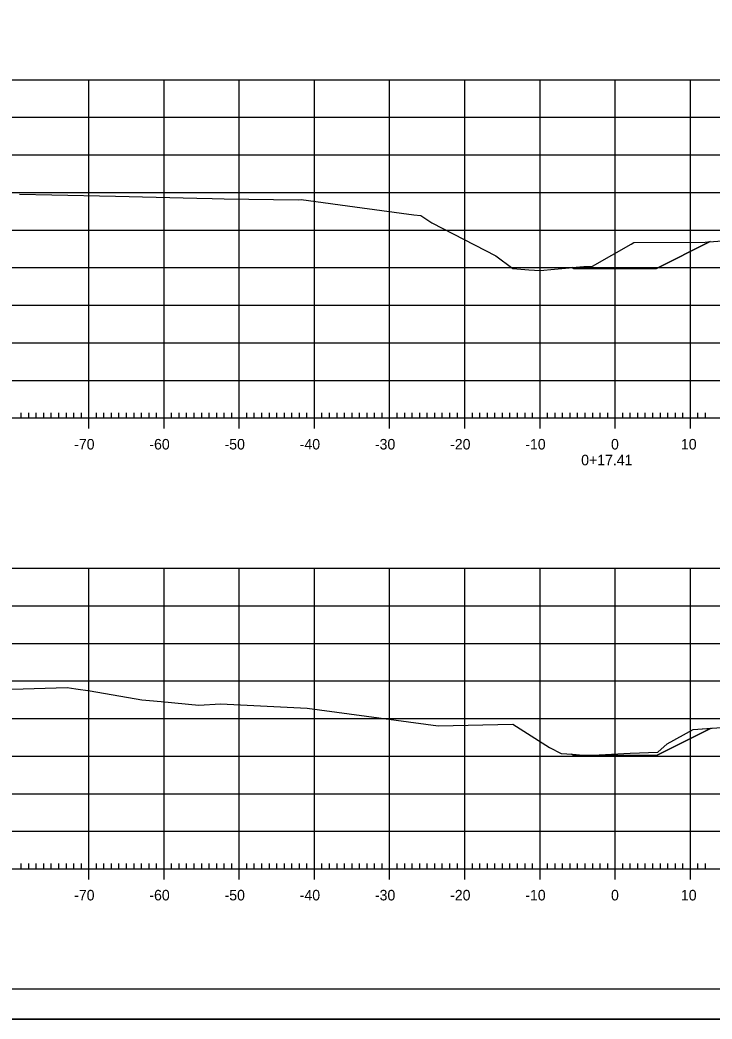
# Model space of a CAD drawing. Extents: x 1360146 to 1361431, y 631444 to 632352.
# Drawn here: x 1361162.4 to 1361254.5, y 631924.1 to 632057 of the extents above; entities that cross this region are included whole.
import ezdxf

# ---------------------------------------------------------------- set-up
doc = ezdxf.new("R2010")
doc.units = 0
for name, color, linetype in [('R_Axis', 7, 'Continuous'), ('R_Axis Annot', 7, 'Continuous'), ('R_Border', 7, 'Continuous'), ('R_Exist Surface', 7, 'Continuous'), ('R_Fin Surface', 7, 'Continuous'), ('R_Grid', 7, 'Continuous'), ('R_No Plot', 7, 'Continuous')]:
    doc.layers.add(name, color=color, linetype=linetype)

msp = doc.modelspace()

# ---------------------------------------------------------------- linework, layer by layer
at = {"layer": 'R_Axis'}
for p, q in [((1361101.6, 632004.09), (1361381.6, 632004.09)), ((1361162.6, 632004.09), (1361162.6, 632004.79)), ((1361163.6, 632004.09), (1361163.6, 632004.79)), ((1361164.6, 632004.09), (1361164.6, 632004.79)), ((1361165.6, 632004.09), (1361165.6, 632004.79)), ((1361166.6, 632004.09), (1361166.6, 632004.79)), ((1361167.6, 632004.09), (1361167.6, 632004.79)), ((1361168.6, 632004.09), (1361168.6, 632004.79)), ((1361169.6, 632004.09), (1361169.6, 632004.79)), ((1361170.6, 632004.09), (1361170.6, 632004.79)), ((1361171.6, 632002.69), (1361171.6, 632004.09)), ((1361172.6, 632004.09), (1361172.6, 632004.79)), ((1361173.6, 632004.09), (1361173.6, 632004.79)), ((1361174.6, 632004.09), (1361174.6, 632004.79)), ((1361175.6, 632004.09), (1361175.6, 632004.79)), ((1361176.6, 632004.09), (1361176.6, 632004.79)), ((1361177.6, 632004.09), (1361177.6, 632004.79)), ((1361178.6, 632004.09), (1361178.6, 632004.79)), ((1361179.6, 632004.09), (1361179.6, 632004.79)), ((1361180.6, 632004.09), (1361180.6, 632004.79)), ((1361181.6, 632002.69), (1361181.6, 632004.09)), ((1361182.6, 632004.09), (1361182.6, 632004.79)), ((1361183.6, 632004.09), (1361183.6, 632004.79)), ((1361184.6, 632004.09), (1361184.6, 632004.79)), ((1361185.6, 632004.09), (1361185.6, 632004.79)), ((1361186.6, 632004.09), (1361186.6, 632004.79)), ((1361187.6, 632004.09), (1361187.6, 632004.79)), ((1361188.6, 632004.09), (1361188.6, 632004.79)), ((1361189.6, 632004.09), (1361189.6, 632004.79)), ((1361190.6, 632004.09), (1361190.6, 632004.79)), ((1361191.6, 632002.69), (1361191.6, 632004.09)), ((1361192.6, 632004.09), (1361192.6, 632004.79)), ((1361193.6, 632004.09), (1361193.6, 632004.79)), ((1361194.6, 632004.09), (1361194.6, 632004.79)), ((1361195.6, 632004.09), (1361195.6, 632004.79)), ((1361196.6, 632004.09), (1361196.6, 632004.79)), ((1361197.6, 632004.09), (1361197.6, 632004.79)), ((1361198.6, 632004.09), (1361198.6, 632004.79)), ((1361199.6, 632004.09), (1361199.6, 632004.79)), ((1361200.6, 632004.09), (1361200.6, 632004.79)), ((1361201.6, 632002.69), (1361201.6, 632004.09)), ((1361202.6, 632004.09), (1361202.6, 632004.79)), ((1361203.6, 632004.09), (1361203.6, 632004.79)), ((1361204.6, 632004.09), (1361204.6, 632004.79)), ((1361205.6, 632004.09), (1361205.6, 632004.79)), ((1361206.6, 632004.09), (1361206.6, 632004.79)), ((1361207.6, 632004.09), (1361207.6, 632004.79)), ((1361208.6, 632004.09), (1361208.6, 632004.79)), ((1361209.6, 632004.09), (1361209.6, 632004.79)), ((1361210.6, 632004.09), (1361210.6, 632004.79)), ((1361211.6, 632002.69), (1361211.6, 632004.09)), ((1361212.6, 632004.09), (1361212.6, 632004.79)), ((1361213.6, 632004.09), (1361213.6, 632004.79)), ((1361214.6, 632004.09), (1361214.6, 632004.79)), ((1361215.6, 632004.09), (1361215.6, 632004.79)), ((1361216.6, 632004.09), (1361216.6, 632004.79)), ((1361217.6, 632004.09), (1361217.6, 632004.79)), ((1361218.6, 632004.09), (1361218.6, 632004.79)), ((1361219.6, 632004.09), (1361219.6, 632004.79)), ((1361220.6, 632004.09), (1361220.6, 632004.79)), ((1361221.6, 632002.69), (1361221.6, 632004.09)), ((1361222.6, 632004.09), (1361222.6, 632004.79)), ((1361223.6, 632004.09), (1361223.6, 632004.79)), ((1361224.6, 632004.09), (1361224.6, 632004.79)), ((1361225.6, 632004.09), (1361225.6, 632004.79)), ((1361226.6, 632004.09), (1361226.6, 632004.79)), ((1361227.6, 632004.09), (1361227.6, 632004.79)), ((1361228.6, 632004.09), (1361228.6, 632004.79)), ((1361229.6, 632004.09), (1361229.6, 632004.79)), ((1361230.6, 632004.09), (1361230.6, 632004.79)), ((1361231.6, 632002.69), (1361231.6, 632004.09)), ((1361232.6, 632004.09), (1361232.6, 632004.79)), ((1361233.6, 632004.09), (1361233.6, 632004.79)), ((1361234.6, 632004.09), (1361234.6, 632004.79)), ((1361235.6, 632004.09), (1361235.6, 632004.79)), ((1361236.6, 632004.09), (1361236.6, 632004.79)), ((1361237.6, 632004.09), (1361237.6, 632004.79)), ((1361238.6, 632004.09), (1361238.6, 632004.79)), ((1361239.6, 632004.09), (1361239.6, 632004.79)), ((1361240.6, 632004.09), (1361240.6, 632004.79)), ((1361241.6, 632002.69), (1361241.6, 632004.09)), ((1361242.6, 632004.09), (1361242.6, 632004.79)), ((1361243.6, 632004.09), (1361243.6, 632004.79)), ((1361244.6, 632004.09), (1361244.6, 632004.79)), ((1361245.6, 632004.09), (1361245.6, 632004.79)), ((1361246.6, 632004.09), (1361246.6, 632004.79)), ((1361247.6, 632004.09), (1361247.6, 632004.79)), ((1361248.6, 632004.09), (1361248.6, 632004.79)), ((1361249.6, 632004.09), (1361249.6, 632004.79)), ((1361250.6, 632004.09), (1361250.6, 632004.79)), ((1361251.6, 632002.69), (1361251.6, 632004.09)), ((1361252.6, 632004.09), (1361252.6, 632004.79)), ((1361253.6, 632004.09), (1361253.6, 632004.79)), ((1361162.6, 631944.09), (1361162.6, 631944.79)), ((1361163.6, 631944.09), (1361163.6, 631944.79)), ((1361164.6, 631944.09), (1361164.6, 631944.79)), ((1361165.6, 631944.09), (1361165.6, 631944.79)), ((1361166.6, 631944.09), (1361166.6, 631944.79)), ((1361167.6, 631944.09), (1361167.6, 631944.79)), ((1361168.6, 631944.09), (1361168.6, 631944.79)), ((1361169.6, 631944.09), (1361169.6, 631944.79)), ((1361170.6, 631944.09), (1361170.6, 631944.79)), ((1361172.6, 631944.09), (1361172.6, 631944.79)), ((1361173.6, 631944.09), (1361173.6, 631944.79)), ((1361174.6, 631944.09), (1361174.6, 631944.79)), ((1361175.6, 631944.09), (1361175.6, 631944.79)), ((1361176.6, 631944.09), (1361176.6, 631944.79)), ((1361177.6, 631944.09), (1361177.6, 631944.79)), ((1361178.6, 631944.09), (1361178.6, 631944.79)), ((1361179.6, 631944.09), (1361179.6, 631944.79)), ((1361180.6, 631944.09), (1361180.6, 631944.79)), ((1361182.6, 631944.09), (1361182.6, 631944.79)), ((1361183.6, 631944.09), (1361183.6, 631944.79)), ((1361184.6, 631944.09), (1361184.6, 631944.79)), ((1361185.6, 631944.09), (1361185.6, 631944.79)), ((1361186.6, 631944.09), (1361186.6, 631944.79)), ((1361187.6, 631944.09), (1361187.6, 631944.79)), ((1361188.6, 631944.09), (1361188.6, 631944.79)), ((1361189.6, 631944.09), (1361189.6, 631944.79)), ((1361190.6, 631944.09), (1361190.6, 631944.79)), ((1361192.6, 631944.09), (1361192.6, 631944.79)), ((1361193.6, 631944.09), (1361193.6, 631944.79)), ((1361194.6, 631944.09), (1361194.6, 631944.79)), ((1361195.6, 631944.09), (1361195.6, 631944.79)), ((1361196.6, 631944.09), (1361196.6, 631944.79)), ((1361197.6, 631944.09), (1361197.6, 631944.79)), ((1361198.6, 631944.09), (1361198.6, 631944.79)), ((1361199.6, 631944.09), (1361199.6, 631944.79)), ((1361200.6, 631944.09), (1361200.6, 631944.79)), ((1361202.6, 631944.09), (1361202.6, 631944.79)), ((1361203.6, 631944.09), (1361203.6, 631944.79)), ((1361204.6, 631944.09), (1361204.6, 631944.79)), ((1361205.6, 631944.09), (1361205.6, 631944.79)), ((1361206.6, 631944.09), (1361206.6, 631944.79)), ((1361207.6, 631944.09), (1361207.6, 631944.79)), ((1361208.6, 631944.09), (1361208.6, 631944.79)), ((1361209.6, 631944.09), (1361209.6, 631944.79)), ((1361210.6, 631944.09), (1361210.6, 631944.79)), ((1361212.6, 631944.09), (1361212.6, 631944.79)), ((1361213.6, 631944.09), (1361213.6, 631944.79)), ((1361214.6, 631944.09), (1361214.6, 631944.79)), ((1361215.6, 631944.09), (1361215.6, 631944.79)), ((1361216.6, 631944.09), (1361216.6, 631944.79)), ((1361217.6, 631944.09), (1361217.6, 631944.79)), ((1361218.6, 631944.09), (1361218.6, 631944.79)), ((1361219.6, 631944.09), (1361219.6, 631944.79)), ((1361220.6, 631944.09), (1361220.6, 631944.79)), ((1361222.6, 631944.09), (1361222.6, 631944.79)), ((1361223.6, 631944.09), (1361223.6, 631944.79)), ((1361224.6, 631944.09), (1361224.6, 631944.79)), ((1361225.6, 631944.09), (1361225.6, 631944.79)), ((1361226.6, 631944.09), (1361226.6, 631944.79)), ((1361227.6, 631944.09), (1361227.6, 631944.79)), ((1361228.6, 631944.09), (1361228.6, 631944.79)), ((1361229.6, 631944.09), (1361229.6, 631944.79)), ((1361230.6, 631944.09), (1361230.6, 631944.79)), ((1361232.6, 631944.09), (1361232.6, 631944.79)), ((1361233.6, 631944.09), (1361233.6, 631944.79)), ((1361234.6, 631944.09), (1361234.6, 631944.79)), ((1361235.6, 631944.09), (1361235.6, 631944.79)), ((1361236.6, 631944.09), (1361236.6, 631944.79)), ((1361237.6, 631944.09), (1361237.6, 631944.79)), ((1361238.6, 631944.09), (1361238.6, 631944.79)), ((1361239.6, 631944.09), (1361239.6, 631944.79)), ((1361240.6, 631944.09), (1361240.6, 631944.79)), ((1361242.6, 631944.09), (1361242.6, 631944.79)), ((1361243.6, 631944.09), (1361243.6, 631944.79)), ((1361244.6, 631944.09), (1361244.6, 631944.79)), ((1361245.6, 631944.09), (1361245.6, 631944.79)), ((1361246.6, 631944.09), (1361246.6, 631944.79)), ((1361247.6, 631944.09), (1361247.6, 631944.79)), ((1361248.6, 631944.09), (1361248.6, 631944.79)), ((1361249.6, 631944.09), (1361249.6, 631944.79)), ((1361250.6, 631944.09), (1361250.6, 631944.79)), ((1361252.6, 631944.09), (1361252.6, 631944.79)), ((1361253.6, 631944.09), (1361253.6, 631944.79)), ((1361101.6, 631944.09), (1361381.6, 631944.09)), ((1361171.6, 631942.69), (1361171.6, 631944.09)), ((1361181.6, 631942.69), (1361181.6, 631944.09)), ((1361191.6, 631942.69), (1361191.6, 631944.09)), ((1361201.6, 631942.69), (1361201.6, 631944.09)), ((1361211.6, 631942.69), (1361211.6, 631944.09)), ((1361221.6, 631942.69), (1361221.6, 631944.09)), ((1361231.6, 631942.69), (1361231.6, 631944.09)), ((1361241.6, 631942.69), (1361241.6, 631944.09)), ((1361251.6, 631942.69), (1361251.6, 631944.09))]:
    msp.add_line(p, q, dxfattribs=at)
at = {"layer": 'R_Border'}
msp.add_line((1361398.78, 631928.09), (1361082.6, 631928.09), dxfattribs=at)
at = {"layer": 'R_Exist Surface'}
for points in [[(1361162.36, 632033.87), (1361166.66, 632033.79), (1361175.13, 632033.58), (1361185.96, 632033.32), (1361187.98, 632033.28), (1361189.58, 632033.24), (1361199.45, 632033.13), (1361199.84, 632033.15), (1361207.93, 632032.04), (1361214.8, 632031.13), (1361215.76, 632031.02), (1361217.23, 632030.06), (1361225.73, 632025.66), (1361227.96, 632023.99), (1361230.11, 632023.81), (1361231.61, 632023.72), (1361233.51, 632023.87), (1361237.44, 632024.24), (1361238.59, 632024.3), (1361243.71, 632027.19), (1361244.08, 632027.44), (1361253.58, 632027.5), (1361260.88, 632028.05)], [(1361159.33, 631968), (1361162.87, 631968.05), (1361168.72, 631968.2), (1361169.85, 631968.04), (1361171.77, 631967.76), (1361178.65, 631966.6), (1361181.23, 631966.37), (1361186.22, 631965.86), (1361189.1, 631966.05), (1361200.64, 631965.46), (1361218.07, 631963.13), (1361227.98, 631963.36), (1361232.86, 631960.25), (1361234.39, 631959.44), (1361235.91, 631959.34), (1361237.81, 631959.18), (1361243.58, 631959.5), (1361247.27, 631959.62), (1361248.52, 631960.74), (1361251.95, 631962.62), (1361257.64, 631963.05)]]:
    msp.add_lwpolyline(points, dxfattribs=at)
at = {"layer": 'R_Fin Surface'}
for points in [[(1361235.89, 632024.09), (1361236.1, 632023.99), (1361241.6, 632023.99), (1361247.1, 632023.99), (1361254.21, 632027.55)], [(1361235.77, 631959.35), (1361236.1, 631959.18), (1361241.6, 631959.18), (1361247.1, 631959.18), (1361254.35, 631962.81)]]:
    msp.add_lwpolyline(points, dxfattribs=at)
at = {"layer": 'R_Grid'}
for p, q in [((1361101.6, 632049.09), (1361381.6, 632049.09)), ((1361171.6, 632004.09), (1361171.6, 632049.09)), ((1361181.6, 632004.09), (1361181.6, 632049.09)), ((1361191.6, 632004.09), (1361191.6, 632049.09)), ((1361201.6, 632004.09), (1361201.6, 632049.09)), ((1361211.6, 632004.09), (1361211.6, 632049.09)), ((1361221.6, 632004.09), (1361221.6, 632049.09)), ((1361231.6, 632004.09), (1361231.6, 632049.09)), ((1361241.6, 632004.09), (1361241.6, 632049.09)), ((1361251.6, 632004.09), (1361251.6, 632049.09)), ((1361101.6, 632044.09), (1361381.6, 632044.09)), ((1361101.6, 632039.09), (1361381.6, 632039.09)), ((1361101.6, 632034.09), (1361381.6, 632034.09)), ((1361101.6, 632029.09), (1361381.6, 632029.09)), ((1361101.6, 632024.09), (1361381.6, 632024.09)), ((1361101.6, 632019.09), (1361381.6, 632019.09)), ((1361101.6, 632014.09), (1361381.6, 632014.09)), ((1361101.6, 632009.09), (1361381.6, 632009.09)), ((1361101.6, 632004.09), (1361381.6, 632004.09)), ((1361101.6, 631984.09), (1361381.6, 631984.09)), ((1361171.6, 631944.09), (1361171.6, 631984.09)), ((1361181.6, 631944.09), (1361181.6, 631984.09)), ((1361191.6, 631944.09), (1361191.6, 631984.09)), ((1361201.6, 631944.09), (1361201.6, 631984.09)), ((1361211.6, 631944.09), (1361211.6, 631984.09)), ((1361221.6, 631944.09), (1361221.6, 631984.09)), ((1361231.6, 631944.09), (1361231.6, 631984.09)), ((1361241.6, 631944.09), (1361241.6, 631984.09)), ((1361251.6, 631944.09), (1361251.6, 631984.09)), ((1361101.6, 631979.09), (1361381.6, 631979.09)), ((1361101.6, 631974.09), (1361381.6, 631974.09)), ((1361101.6, 631969.09), (1361381.6, 631969.09)), ((1361101.6, 631964.09), (1361381.6, 631964.09)), ((1361101.6, 631959.09), (1361381.6, 631959.09)), ((1361101.6, 631954.09), (1361381.6, 631954.09)), ((1361101.6, 631949.09), (1361381.6, 631949.09)), ((1361101.6, 631944.09), (1361381.6, 631944.09))]:
    msp.add_line(p, q, dxfattribs=at)
at = {"layer": 'R_No Plot'}
msp.add_line((1361070.2, 631924.11), (1361403.53, 631924.11), dxfattribs=at)
for points in [[(1361070.19, 632137.45), (1361403.53, 632137.45), (1361403.53, 631924.11), (1361070.19, 631924.11)], [(1361316.52, 632133.55), (1361316.52, 632123.67), (1361352.25, 632123.67), (1361352.25, 632120.75), (1361375.45, 632120.75), (1361375.45, 632096.42), (1361398.78, 632096.42), (1361398.78, 631928.09), (1361082.6, 631928.09), (1361082.6, 632133.55)], [(1361235.89, 632024.09), (1361237.44, 632024.24), (1361238.59, 632024.3), (1361243.71, 632027.19), (1361244.08, 632027.44), (1361253.58, 632027.5), (1361254.21, 632027.55), (1361247.1, 632023.99), (1361241.6, 632023.99), (1361236.1, 632023.99)], [(1361235.77, 631959.35), (1361235.91, 631959.34), (1361237.81, 631959.18), (1361243.58, 631959.5), (1361247.27, 631959.62), (1361248.52, 631960.74), (1361251.95, 631962.62), (1361254.35, 631962.81), (1361247.1, 631959.18), (1361241.6, 631959.18), (1361236.1, 631959.18)]]:
    msp.add_lwpolyline(points, close=True, dxfattribs=at)

# ---------------------------------------------------------------- texts
at = {"layer": 'R_Axis Annot'}
for s, p in [('-70', (1361169.64, 631999.89)), ('-60', (1361179.64, 631999.89)), ('-50', (1361189.64, 631999.89)), ('-40', (1361199.64, 631999.89)), ('-30', (1361209.64, 631999.89)), ('-20', (1361219.64, 631999.89)), ('-10', (1361229.64, 631999.89)), ('0', (1361241.04, 631999.89)), ('10', (1361250.34, 631999.89)), ('0+17.41', (1361237.07, 631997.79)), ('-70', (1361169.64, 631939.89)), ('-60', (1361179.64, 631939.89)), ('-50', (1361189.64, 631939.89)), ('-40', (1361199.64, 631939.89)), ('-30', (1361209.64, 631939.89)), ('-20', (1361219.64, 631939.89)), ('-10', (1361229.64, 631939.89)), ('0', (1361241.04, 631939.89)), ('10', (1361250.34, 631939.89))]:
    msp.add_text(s, height=1.4, dxfattribs=at).set_placement(p)

doc.saveas('drawing.dxf')
